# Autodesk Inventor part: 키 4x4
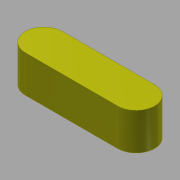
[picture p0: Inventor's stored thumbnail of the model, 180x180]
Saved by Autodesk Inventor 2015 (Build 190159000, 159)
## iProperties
Created: 2014-10
Part Number: 키 4x4
Document SubType Name: Modeling
Designer: KYOUNG IL JANG
Density: 7.86 g/cm^3
Mass: 1.65269 g
Surface Area: 2.35398 cm^2
Volume: 0.210265 cm^3
Material: 강철, 연강
Appearance: 노란색
Author: SeoGD™ [www.esajin.kr]
Revision Number: 1
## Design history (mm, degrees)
sketch "스케치1"
  geometry: L1 (-5, -2)-(5, -2); L2 (5, 2)-(-5, 2); A1 r 2 centre (5, 0) between (5, -2) and (5, 2); A2 r 2 centre (-5, 0) between (-5, 2) and (-5, -2); 2 further points
  constraints: 4 end point, 4 point on circle, 4 tangent, 2 centre point, 1 horizontal, 1 horizontal alignment, 1 midpoint, 1 parallel, 1 vertical alignment
  dimensions: "d0" = 4 distance between parallel lines of L1 L2; "d1" = 14 dimension on A1 A2
extrude "돌출1" new body sketch "스케치1" stored distance "d2" = 4; taper "d3" = 0 deg
node "솔리드1"
